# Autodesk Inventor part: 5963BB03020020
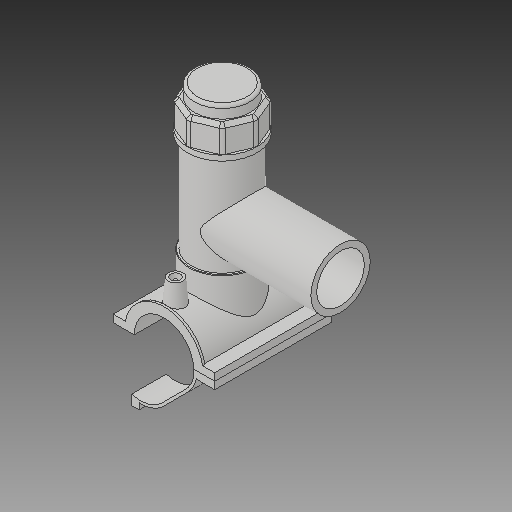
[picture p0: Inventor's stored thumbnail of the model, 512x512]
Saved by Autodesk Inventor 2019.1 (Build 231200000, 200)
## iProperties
Created: 2017-07
Part Number: 5963BB03020020
Material: Generic
Description: PLASSON TAPPING SADDLE 2''IPS x 2''IPS
Document SubType Name: Modeling
Designer: KIM
Mass: 1712.7 g
Surface Area: 2671.49 cm^2
Volume: 1712.7 cm^3
Density: 1 g/cm^3
Appearance: Default
Author: KIM
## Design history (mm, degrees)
derived "5963B.ipt"
feature "Solid1::5963B.ipt"
feature "Solid2::5963B.ipt"
feature "Solid4::5963B.ipt"
feature "Solid5::5963B.ipt"
tag "TaggingFeature1"
body "Solid1"
body "Solid2"
other parameters: "d0" = 60.1, "d2" = 102.87, "d3" = 15.025, "d4" = 118.11, "d5" = 0, "d6" = 0.1, "d8" = 0, "d19" = 6, "d20" = 6, "d21" = 70.866, "d23" = 0, "d24" = 35.433, "d26" = 0, "d29" = 3, "d30" = 20.03333, "d31" = 6, "d32" = 0, "d33" = 0, "d34" = 0.6, "d40" = 40.6276, "d41" = 54.09, "d43" = 0, "d45" = 0, "d47" = 109.931, "d70" = 15, "d72" = 0, "d73" = 6, "d75" = 5, "d76" = 0, "d77" = 3.005, "d78" = 60.05, "d79" = 15, "d80" = 47.244, "d82" = 5 deg, "d84" = 4, "d85" = 14, "d86" = 0, "d87" = 3, "d88" = 0, "d89" = 1, "d90" = 1, "d91" = 94.488, "d92" = 0, "d93" = 0.5, "d94" = 31.63158, "d96" = 79.6926, "d97" = 2.3622, "d98" = 0, "d102" = 0.601, "d120" = 140 deg, "d121" = 24.228, "d122" = 20 deg, "d123" = 156.26, "d124" = 46.878, "d126" = 0, "d143" = 61.903, "d145" = 13.86923, "d149" = 0.9015, "d150" = 15.25615, "d153" = 118.11, "d154" = 0, "d156" = 39.065, "d157" = 160 deg, "d159" = 3.606, "d161" = 0.9015, "d162" = 70.866, "d163" = 0, "d164" = 30.05, "d167" = 6.01, "d168" = 38.1122, "d170" = 3.2805, "d172" = 0, "d173" = 1, "d175" = 30.05, "d176" = 20 deg, "d177" = 4.207, "d178" = 18.03, "d180" = 0, "d183" = 7.212, "d184" = 3.3656, "d185" = 38.38575, "d186" = 38.38575, "d187" = 39.065, "d188" = 5.409, "d189" = 4.207, "d190" = 0, "d191" = 58.5975, "d193" = 6.1236, "d194" = 4.13385, "d195" = 90 deg, "d197" = 0, "d199" = 0, "d200" = 9.015, "d202" = 0, "d203" = 177.038, "d204" = 66.80115, "d205" = 49.2219, "d206" = 62.06828, "d207" = 132.7785, "d208" = 138.08964, "d209" = 164.64534, "d210" = 60.47262, "d211" = 70.317, "d212" = 56.2536, "d213" = 31.4766, "d216" = 0, "d217" = 6.01, "d218" = 3.005, "d219" = 0.601, "d222" = 60.1, "d224" = 0, "d230" = 3.606, "d233" = 6, "d236" = 51.435, "d237" = 35.433, "d238" = 6.02433, "d240" = 35.433, "d241" = 35.433, "d242" = 35.433, "d243" = 6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
